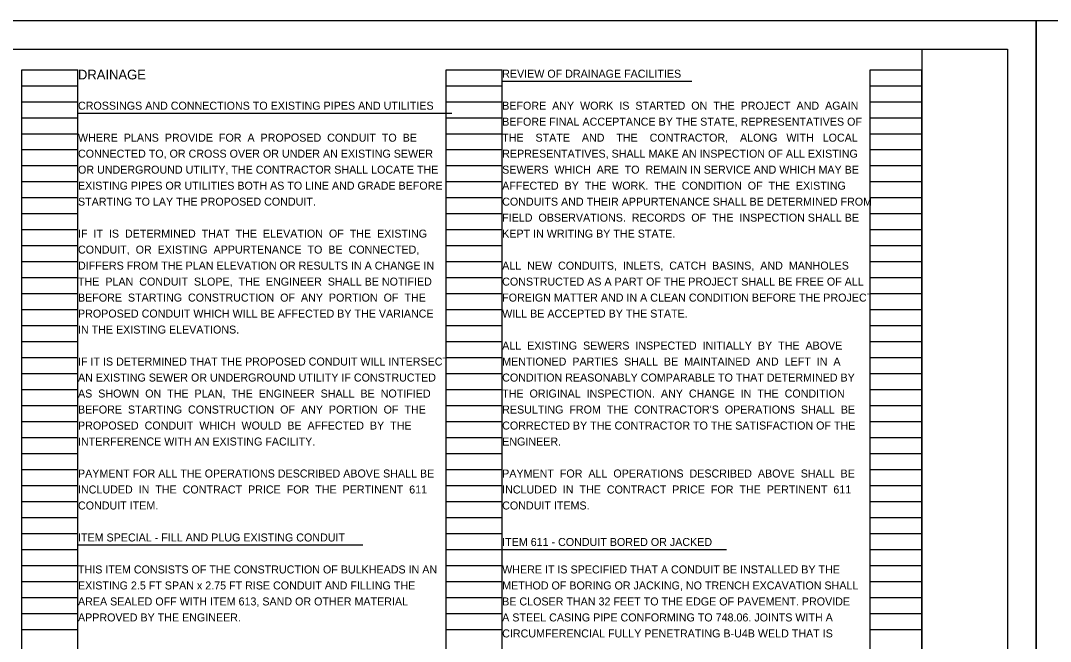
# Model space of a CAD drawing. Extents: x 0 to 102, y 0 to 22.
# Drawn here: x 50.24 to 68.25, y 11.13 to 22 of the extents above; entities that cross this region are included whole.
import ezdxf

# ---------------------------------------------------------------- set-up
doc = ezdxf.new("R2010")
doc.units = 0
doc.layers.add('SC_Scratch1', color=7, linetype='Continuous')
doc.layers.add('SH_Text', color=7, linetype='Continuous')

msp = doc.modelspace()

# ---------------------------------------------------------------- linework, layer by layer
at = {"layer": 'SC_Scratch1'}
for p, q in [((50.26, 0.98), (50.26, 21.14)), ((50.26, 21.14), (51.24, 21.14)), ((51.24, 0.98), (51.24, 21.14)), ((57.68, 0.98), (57.68, 21.14)), ((57.68, 21.14), (58.66, 21.14)), ((58.66, 0.98), (58.66, 21.14)), ((65.1, 0.98), (65.1, 21.14)), ((65.1, 21.14), (66, 21.14)), ((66, 0.98), (66, 21.14)), ((50.26, 20.86), (51.24, 20.86)), ((57.68, 20.86), (58.66, 20.86)), ((65.1, 20.86), (66, 20.86)), ((50.26, 20.58), (51.24, 20.58)), ((57.68, 20.58), (58.66, 20.58)), ((65.1, 20.58), (66, 20.58)), ((50.26, 20.3), (51.24, 20.3)), ((57.68, 20.3), (58.66, 20.3)), ((65.1, 20.3), (66, 20.3)), ((50.26, 20.02), (51.24, 20.02)), ((57.68, 20.02), (58.66, 20.02)), ((65.1, 20.02), (66, 20.02)), ((50.26, 19.74), (51.24, 19.74)), ((57.68, 19.74), (58.66, 19.74)), ((65.1, 19.74), (66, 19.74)), ((50.26, 19.46), (51.24, 19.46)), ((57.68, 19.46), (58.66, 19.46)), ((65.1, 19.46), (66, 19.46)), ((50.26, 19.18), (51.24, 19.18)), ((57.68, 19.18), (58.66, 19.18)), ((65.1, 19.18), (66, 19.18)), ((50.26, 18.9), (51.24, 18.9)), ((57.68, 18.9), (58.66, 18.9)), ((65.1, 18.9), (66, 18.9)), ((50.26, 18.62), (51.24, 18.62)), ((57.68, 18.62), (58.66, 18.62)), ((65.1, 18.62), (66, 18.62)), ((50.26, 18.34), (51.24, 18.34)), ((57.68, 18.34), (58.66, 18.34)), ((65.1, 18.34), (66, 18.34)), ((50.26, 18.06), (51.24, 18.06)), ((57.68, 18.06), (58.66, 18.06)), ((65.1, 18.06), (66, 18.06)), ((50.26, 17.78), (51.24, 17.78)), ((57.68, 17.78), (58.66, 17.78)), ((65.1, 17.78), (66, 17.78)), ((50.26, 17.5), (51.24, 17.5)), ((57.68, 17.5), (58.66, 17.5)), ((65.1, 17.5), (66, 17.5)), ((50.26, 17.22), (51.24, 17.22)), ((57.68, 17.22), (58.66, 17.22)), ((65.1, 17.22), (66, 17.22)), ((50.26, 16.94), (51.24, 16.94)), ((57.68, 16.94), (58.66, 16.94)), ((65.1, 16.94), (66, 16.94)), ((50.26, 16.66), (51.24, 16.66)), ((57.68, 16.66), (58.66, 16.66)), ((65.1, 16.66), (66, 16.66)), ((50.26, 16.38), (51.24, 16.38)), ((57.68, 16.38), (58.66, 16.38)), ((65.1, 16.38), (66, 16.38)), ((50.26, 16.1), (51.24, 16.1)), ((57.68, 16.1), (58.66, 16.1)), ((65.1, 16.1), (66, 16.1)), ((50.26, 15.82), (51.24, 15.82)), ((57.68, 15.82), (58.66, 15.82)), ((65.1, 15.82), (66, 15.82)), ((50.26, 15.54), (51.24, 15.54)), ((57.68, 15.54), (58.66, 15.54)), ((65.1, 15.54), (66, 15.54)), ((50.26, 15.26), (51.24, 15.26)), ((57.68, 15.26), (58.66, 15.26)), ((65.1, 15.26), (66, 15.26)), ((50.26, 14.98), (51.24, 14.98)), ((57.68, 14.98), (58.66, 14.98)), ((65.1, 14.98), (66, 14.98)), ((50.26, 14.7), (51.24, 14.7)), ((57.68, 14.7), (58.66, 14.7)), ((65.1, 14.7), (66, 14.7)), ((50.26, 14.42), (51.24, 14.42)), ((57.68, 14.42), (58.66, 14.42)), ((65.1, 14.42), (66, 14.42)), ((50.26, 14.14), (51.24, 14.14)), ((57.68, 14.14), (58.66, 14.14)), ((65.1, 14.14), (66, 14.14)), ((50.26, 13.86), (51.24, 13.86)), ((57.68, 13.86), (58.66, 13.86)), ((65.1, 13.86), (66, 13.86)), ((50.26, 13.58), (51.24, 13.58)), ((57.68, 13.58), (58.66, 13.58)), ((65.1, 13.58), (66, 13.58)), ((50.26, 13.3), (51.24, 13.3)), ((57.68, 13.3), (58.66, 13.3)), ((65.1, 13.3), (66, 13.3)), ((50.26, 13.02), (51.24, 13.02)), ((57.68, 13.02), (58.66, 13.02)), ((65.1, 13.02), (66, 13.02)), ((50.26, 12.74), (51.24, 12.74)), ((57.68, 12.74), (58.66, 12.74)), ((65.1, 12.74), (66, 12.74)), ((50.26, 12.46), (51.24, 12.46)), ((57.68, 12.46), (58.66, 12.46)), ((65.1, 12.46), (66, 12.46)), ((50.26, 12.18), (51.24, 12.18)), ((57.68, 12.18), (58.66, 12.18)), ((65.1, 12.18), (66, 12.18)), ((50.26, 11.9), (51.24, 11.9)), ((57.68, 11.9), (58.66, 11.9)), ((65.1, 11.9), (66, 11.9)), ((50.26, 11.62), (51.24, 11.62)), ((57.68, 11.62), (58.66, 11.62)), ((65.1, 11.62), (66, 11.62)), ((50.26, 11.34), (51.24, 11.34)), ((57.68, 11.34), (58.66, 11.34)), ((65.1, 11.34), (66, 11.34))]:
    msp.add_line(p, q, dxfattribs=at)
for points in [[(34, 22), (68, 22), (68, 0), (34, 0)], [(68, 22), (102, 22), (102, 0), (68, 0)], [(34.5, 21.5), (67.5, 21.5), (67.5, 0.5), (34.5, 0.5)], [(35.5, 21.5), (66, 21.5), (66, 0.5), (35.5, 0.5)]]:
    msp.add_lwpolyline(points, close=True, dxfattribs=at)
at = {"layer": 'SH_Text'}
for p, q in [((58.66, 20.939), (61.98, 20.939)), ((51.24, 20.379), (57.781, 20.379)), ((51.24, 12.819), (56.223, 12.819)), ((58.66, 12.74), (62.585, 12.74))]:
    msp.add_line(p, q, dxfattribs=at)

# ---------------------------------------------------------------- texts
for s, height, p in [('DRAINAGE', 0.17, (51.24, 20.97)), ('REVIEW OF DRAINAGE FACILITIES', 0.14, (58.66, 21)), ('CROSSINGS AND CONNECTIONS TO EXISTING PIPES AND UTILITIES', 0.14, (51.24, 20.44)), ('BEFORE  ANY  WORK  IS  STARTED  ON  THE  PROJECT  AND  AGAIN', 0.14, (58.66, 20.44)), ('BEFORE FINAL ACCEPTANCE BY THE STATE, REPRESENTATIVES OF', 0.14, (58.66, 20.16)), ('WHERE  PLANS  PROVIDE  FOR  A  PROPOSED  CONDUIT  TO  BE', 0.14, (51.24, 19.88)), ('THE    STATE    AND    THE    CONTRACTOR,    ALONG   WITH   LOCAL', 0.14, (58.66, 19.88)), ('CONNECTED TO, OR CROSS OVER OR UNDER AN EXISTING SEWER', 0.14, (51.24, 19.6)), ('REPRESENTATIVES, SHALL MAKE AN INSPECTION OF ALL EXISTING', 0.14, (58.66, 19.6)), ('OR UNDERGROUND UTILITY, THE CONTRACTOR SHALL LOCATE THE', 0.14, (51.24, 19.32)), ('SEWERS  WHICH  ARE  TO  REMAIN IN SERVICE AND WHICH MAY BE', 0.14, (58.66, 19.32)), ('EXISTING PIPES OR UTILITIES BOTH AS TO LINE AND GRADE BEFORE', 0.14, (51.24, 19.04)), ('AFFECTED  BY  THE  WORK.  THE  CONDITION  OF  THE  EXISTING', 0.14, (58.66, 19.04)), ('STARTING TO LAY THE PROPOSED CONDUIT.', 0.14, (51.24, 18.76)), ('CONDUITS AND THEIR APPURTENANCE SHALL BE DETERMINED FROM', 0.14, (58.66, 18.76)), ('FIELD  OBSERVATIONS.  RECORDS  OF  THE  INSPECTION SHALL BE', 0.14, (58.66, 18.48)), ('IF  IT  IS  DETERMINED  THAT  THE  ELEVATION  OF  THE  EXISTING', 0.14, (51.24, 18.2)), ('KEPT IN WRITING BY THE STATE.', 0.14, (58.66, 18.2)), ('CONDUIT,  OR  EXISTING  APPURTENANCE  TO  BE  CONNECTED,', 0.14, (51.24, 17.92)), ('DIFFERS FROM THE PLAN ELEVATION OR RESULTS IN A CHANGE IN', 0.14, (51.24, 17.64)), ('ALL  NEW  CONDUITS,  INLETS,  CATCH  BASINS,  AND  MANHOLES', 0.14, (58.66, 17.64)), ('THE  PLAN  CONDUIT  SLOPE,  THE  ENGINEER  SHALL BE NOTIFIED', 0.14, (51.24, 17.36)), ('CONSTRUCTED AS A PART OF THE PROJECT SHALL BE FREE OF ALL', 0.14, (58.66, 17.36)), ('BEFORE  STARTING  CONSTRUCTION  OF  ANY  PORTION  OF  THE', 0.14, (51.24, 17.08)), ('FOREIGN MATTER AND IN A CLEAN CONDITION BEFORE THE PROJECT', 0.14, (58.66, 17.08)), ('PROPOSED CONDUIT WHICH WILL BE AFFECTED BY THE VARIANCE', 0.14, (51.24, 16.8)), ('WILL BE ACCEPTED BY THE STATE.', 0.14, (58.66, 16.8)), ('IN THE EXISTING ELEVATIONS.', 0.14, (51.24, 16.52)), ('ALL  EXISTING  SEWERS  INSPECTED  INITIALLY  BY  THE  ABOVE', 0.14, (58.66, 16.24)), ('IF IT IS DETERMINED THAT THE PROPOSED CONDUIT WILL INTERSECT', 0.14, (51.24, 15.96)), ('MENTIONED  PARTIES  SHALL  BE  MAINTAINED  AND  LEFT  IN  A', 0.14, (58.66, 15.96)), ('AN EXISTING SEWER OR UNDERGROUND UTILITY IF CONSTRUCTED', 0.14, (51.24, 15.68)), ('CONDITION REASONABLY COMPARABLE TO THAT DETERMINED BY', 0.14, (58.66, 15.68)), ('AS  SHOWN  ON  THE  PLAN,  THE  ENGINEER  SHALL  BE  NOTIFIED', 0.14, (51.24, 15.4)), ('THE  ORIGINAL  INSPECTION.  ANY  CHANGE  IN  THE  CONDITION', 0.14, (58.66, 15.4)), ('BEFORE  STARTING  CONSTRUCTION  OF  ANY  PORTION  OF  THE', 0.14, (51.24, 15.12)), ("RESULTING  FROM  THE  CONTRACTOR'S  OPERATIONS  SHALL  BE", 0.14, (58.66, 15.12)), ('PROPOSED  CONDUIT  WHICH  WOULD  BE  AFFECTED  BY  THE', 0.14, (51.24, 14.84)), ('CORRECTED BY THE CONTRACTOR TO THE SATISFACTION OF THE', 0.14, (58.66, 14.84)), ('INTERFERENCE WITH AN EXISTING FACILITY.', 0.14, (51.24, 14.56)), ('ENGINEER.', 0.14, (58.66, 14.56)), ('PAYMENT FOR ALL THE OPERATIONS DESCRIBED ABOVE SHALL BE', 0.14, (51.24, 14)), ('PAYMENT  FOR  ALL  OPERATIONS  DESCRIBED  ABOVE  SHALL  BE', 0.14, (58.66, 14)), ('INCLUDED  IN  THE  CONTRACT  PRICE  FOR  THE  PERTINENT  611', 0.14, (51.24, 13.72)), ('INCLUDED  IN  THE  CONTRACT  PRICE  FOR  THE  PERTINENT  611', 0.14, (58.66, 13.72)), ('CONDUIT ITEM.', 0.14, (51.24, 13.44)), ('CONDUIT ITEMS.', 0.14, (58.66, 13.44)), ('ITEM SPECIAL - FILL AND PLUG EXISTING CONDUIT', 0.14, (51.24, 12.88)), ('ITEM 611 - CONDUIT BORED OR JACKED', 0.14, (58.66, 12.801)), ('THIS ITEM CONSISTS OF THE CONSTRUCTION OF BULKHEADS IN AN ', 0.14, (51.24, 12.32)), ('WHERE IT IS SPECIFIED THAT A CONDUIT BE INSTALLED BY THE ', 0.14, (58.66, 12.32)), ('EXISTING 2.5 FT SPAN x 2.75 FT RISE CONDUIT AND FILLING THE', 0.14, (51.24, 12.04)), ('METHOD OF BORING OR JACKING, NO TRENCH EXCAVATION SHALL ', 0.14, (58.66, 12.04)), ('AREA SEALED OFF WITH ITEM 613, SAND OR OTHER MATERIAL', 0.14, (51.24, 11.76)), ('BE CLOSER THAN 32 FEET TO THE EDGE OF PAVEMENT. PROVIDE ', 0.14, (58.66, 11.76)), ('APPROVED BY THE ENGINEER.', 0.14, (51.24, 11.48)), ('A STEEL CASING PIPE CONFORMING TO 748.06. JOINTS WITH A ', 0.14, (58.66, 11.48)), ('CIRCUMFERENCIAL FULLY PENETRATING B-U4B WELD THAT IS ', 0.14, (58.66, 11.2))]:
    msp.add_text(s, height=height, dxfattribs=at).set_placement(p)

doc.saveas('drawing.dxf')
